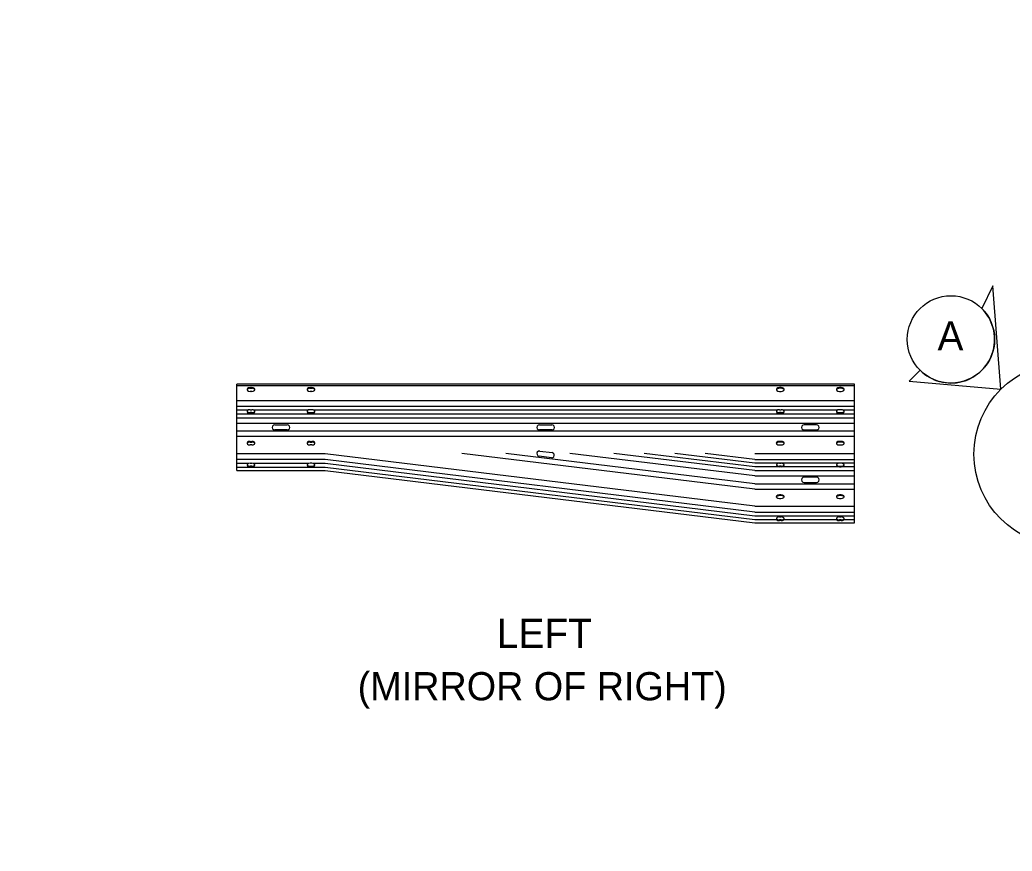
# Model space of a CAD drawing. Extents: x 34446 to 262144, y 33903 to 262144.
# Drawn here: x 101317 to 101879, y 100430 to 100902 of the extents above; entities that cross this region are included whole.
import ezdxf

# ---------------------------------------------------------------- set-up
doc = ezdxf.new("R2010")
doc.units = 0
for name, color, linetype in [('Level 12', 7, 'Continuous'), ('Level 15', 7, 'Continuous'), ('Level 20', 7, 'Continuous'), ('Level 5', 7, 'Continuous'), ('Level 9', 7, 'Continuous')]:
    doc.layers.add(name, color=color, linetype=linetype)

msp = doc.modelspace()

# ---------------------------------------------------------------- linework, layer by layer
at = {"layer": 'Level 12'}
for p, q in [((101790.09, 100695.07), (101440.09, 100695.07)), ((101440.09, 100646.07), (101440.09, 100695.07)), ((101790.09, 100616.5), (101790.09, 100695.07)), ((101440.09, 100646.07), (101490.09, 100646.07)), ((101490.09, 100646.07), (101733.71, 100616.5)), ((101733.71, 100616.5), (101790.09, 100616.5))]:
    msp.add_line(p, q, dxfattribs=at)
for points in [[(101461.59, 100672.06), (101468.59, 100672.06)], [(101468.59, 100669.08), (101461.59, 100669.08)], [(101611.59, 100672.06), (101618.59, 100672.06)], [(101618.59, 100669.08), (101611.59, 100669.08)], [(101768.59, 100672.06), (101761.59, 100672.06)], [(101761.59, 100669.08), (101768.59, 100669.08)], [(101611.77, 100657.16), (101618.71, 100656.32)], [(101618.35, 100653.35), (101611.4, 100654.2)], [(101768.59, 100642.3), (101761.59, 100642.3)], [(101761.59, 100639.32), (101768.59, 100639.32)]]:
    msp.add_lwpolyline(points, dxfattribs=at)
for centre, major_axis, start_param, end_param in [((101461.59, 100670.57), (-1.5, 0), 4.712389, 7.853982), ((101468.59, 100670.57), (-1.5, 0), 1.570796, 4.712389), ((101611.59, 100670.57), (-1.5, 0), 4.712389, 7.853982), ((101618.59, 100670.57), (-1.5, 0), 1.570796, 4.712389), ((101761.59, 100670.57), (1.5, 0), 1.570796, 4.712389), ((101768.59, 100670.57), (1.5, 0), 4.712389, 7.853982), ((101611.58, 100655.68), (-1.5, 0), 4.590604, 7.732197), ((101618.53, 100654.83), (-1.5, 0), 1.449011, 4.590604), ((101761.59, 100640.81), (1.5, 0), 1.570796, 4.712389), ((101768.59, 100640.81), (1.5, 0), 4.712389, 7.853982)]:
    msp.add_ellipse(centre, major_axis=major_axis, ratio=0.994924, start_param=start_param, end_param=end_param, dxfattribs=at)
at = {"layer": 'Level 15'}
msp.add_circle((101909.84, 100655.41), 52, dxfattribs=at)
at = {"layer": 'Level 5'}
msp.add_spline([(100965.33, 100576.22), (100979.73, 100581.07), (100976.65, 100587.06), (100980.64, 100590.15), (100978.82, 100594.87), (100978.82, 100594.87), (100972.35, 100605.26)], degree=3, dxfattribs=at)
at = {"layer": 'Level 9'}
for p, q in [((101868.48, 100750.85), (101862.3, 100737.95)), ((101873.07, 100692.18), (101868.48, 100750.85)), ((101827.29, 100702.95), (101821.11, 100696.76)), ((101821.11, 100696.76), (101873.07, 100692.18)), ((101790.09, 100694.19), (101440.09, 100694.19)), ((101790.09, 100694.19), (101440.09, 100694.19)), ((101447.66, 100693.1), (101448.53, 100693.1)), ((101447.66, 100692.7), (101448.53, 100692.7)), ((101448.53, 100690.98), (101447.66, 100690.98)), ((101481.66, 100693.1), (101482.53, 100693.1)), ((101481.66, 100692.7), (101482.53, 100692.7)), ((101482.53, 100690.98), (101481.66, 100690.98)), ((101748.53, 100693.1), (101747.66, 100693.1)), ((101748.53, 100692.7), (101747.66, 100692.7)), ((101747.66, 100690.98), (101748.53, 100690.98)), ((101782.53, 100693.1), (101781.66, 100693.1)), ((101782.53, 100692.7), (101781.66, 100692.7)), ((101781.66, 100690.98), (101782.53, 100690.98)), ((101790.09, 100685.65), (101440.09, 100685.65)), ((101790.09, 100682.41), (101440.09, 100682.41)), ((101446.31, 100680.22), (101440.09, 100680.22)), ((101447.66, 100680.56), (101448.53, 100680.56)), ((101480.31, 100680.22), (101449.88, 100680.22)), ((101482.53, 100680.56), (101481.66, 100680.56)), ((101746.31, 100680.22), (101483.88, 100680.22)), ((101747.66, 100680.56), (101748.53, 100680.56)), ((101780.31, 100680.22), (101749.88, 100680.22)), ((101782.53, 100680.56), (101781.66, 100680.56)), ((101790.09, 100680.22), (101783.88, 100680.22)), ((101790.09, 100678.02), (101440.09, 100678.02)), ((101790.09, 100675.83), (101440.09, 100675.83)), ((101448.53, 100678.92), (101447.66, 100678.92)), ((101448.53, 100678.51), (101447.66, 100678.51)), ((101481.66, 100678.92), (101482.53, 100678.92)), ((101481.66, 100678.51), (101482.53, 100678.51)), ((101748.53, 100678.92), (101747.66, 100678.92)), ((101748.53, 100678.51), (101747.66, 100678.51)), ((101781.66, 100678.92), (101782.53, 100678.92)), ((101781.66, 100678.51), (101782.53, 100678.51)), ((101790.09, 100672.8), (101440.09, 100672.8)), ((101790.09, 100668.35), (101440.09, 100668.35)), ((101790.09, 100665.32), (101440.09, 100665.32)), ((101447.66, 100662.63), (101448.53, 100662.63)), ((101481.69, 100662.63), (101482.56, 100662.63)), ((101748.5, 100662.63), (101747.63, 100662.63)), ((101782.53, 100662.63), (101781.66, 100662.63)), ((101447.66, 100662.23), (101448.53, 100662.23)), ((101448.53, 100660.58), (101447.66, 100660.58)), ((101481.69, 100662.23), (101482.56, 100662.23)), ((101482.56, 100660.58), (101481.69, 100660.58)), ((101748.5, 100662.23), (101747.63, 100662.23)), ((101747.63, 100660.58), (101748.5, 100660.58)), ((101782.53, 100662.23), (101781.66, 100662.23)), ((101781.66, 100660.58), (101782.53, 100660.58)), ((101490.09, 100655.5), (101440.09, 100655.5)), ((101490.09, 100655.5), (101440.09, 100655.5)), ((101490.09, 100652.26), (101440.09, 100652.26)), ((101490.09, 100652.26), (101440.09, 100652.26)), ((101733.71, 100625.83), (101490.09, 100655.5)), ((101733.71, 100622.4), (101490.09, 100652.26)), ((101733.71, 100635.57), (101567.67, 100655.79)), ((101733.71, 100638.6), (101592.56, 100655.79)), ((101733.71, 100643.02), (101628.86, 100655.79)), ((101733.71, 100646.05), (101653.75, 100655.79)), ((101733.71, 100648.15), (101671, 100655.79)), ((101733.71, 100650.25), (101688.25, 100655.79)), ((101733.71, 100652.35), (101705.5, 100655.79)), ((101733.71, 100655.79), (101790.09, 100655.79)), ((101733.71, 100652.35), (101790.09, 100652.35)), ((101446.68, 100650.07), (101440.09, 100650.07)), ((101490.09, 100647.87), (101440.09, 100647.87)), ((101490.09, 100647.87), (101440.09, 100647.87)), ((101447.66, 100650.23), (101448.53, 100650.23)), ((101448.53, 100648.59), (101447.66, 100648.59)), ((101448.53, 100648.18), (101447.66, 100648.18)), ((101480.68, 100650.07), (101449.51, 100650.07)), ((101482.53, 100650.23), (101481.66, 100650.23)), ((101481.66, 100648.59), (101482.53, 100648.59)), ((101481.66, 100648.18), (101482.53, 100648.18)), ((101490.09, 100650.07), (101483.51, 100650.07)), ((101733.71, 100620.3), (101490.09, 100650.07)), ((101733.71, 100618.19), (101490.09, 100647.87)), ((101790.09, 100650.25), (101733.71, 100650.25)), ((101790.09, 100648.15), (101733.71, 100648.15)), ((101733.71, 100646.05), (101790.09, 100646.05)), ((101747.66, 100650.23), (101748.53, 100650.23)), ((101748.53, 100648.59), (101747.66, 100648.59)), ((101748.53, 100648.18), (101747.66, 100648.18)), ((101782.53, 100650.23), (101781.66, 100650.23)), ((101781.66, 100648.59), (101782.53, 100648.59)), ((101781.66, 100648.18), (101782.53, 100648.18)), ((101733.71, 100643.02), (101790.09, 100643.02)), ((101733.71, 100638.6), (101790.09, 100638.6)), ((101733.71, 100635.57), (101790.09, 100635.57)), ((101748.47, 100632.3), (101747.6, 100632.3)), ((101748.47, 100631.9), (101747.6, 100631.9)), ((101747.6, 100630.25), (101748.47, 100630.25)), ((101782.53, 100632.3), (101781.66, 100632.3)), ((101782.53, 100631.9), (101781.66, 100631.9)), ((101781.66, 100630.25), (101782.53, 100630.25)), ((101733.71, 100625.83), (101790.09, 100625.83)), ((101733.71, 100622.4), (101790.09, 100622.4)), ((101790.09, 100620.3), (101733.71, 100620.3)), ((101746.11, 100618.19), (101733.71, 100618.19)), ((101747.66, 100619.8), (101748.53, 100619.8)), ((101748.53, 100618.08), (101747.66, 100618.08)), ((101748.53, 100617.68), (101747.66, 100617.68)), ((101780.11, 100618.19), (101750.07, 100618.19)), ((101781.66, 100619.8), (101782.53, 100619.8)), ((101782.53, 100618.08), (101781.66, 100618.08)), ((101782.53, 100617.68), (101781.66, 100617.68)), ((101790.09, 100618.19), (101784.07, 100618.19))]:
    msp.add_line(p, q, dxfattribs=at)
msp.add_circle((101844.8, 100720.45), 24.75, dxfattribs=at)
msp.add_arc((101844.8, 100720.45), 24.75, 224.9978, 45.0022, dxfattribs=at)
for centre, major_axis, ratio, start_param, end_param in [((101447.66, 100692.04), (-1.8, 0), 0.587551, 4.712389, 7.853982), ((101447.66, 100691.64), (-1.8, 0), 0.587551, 4.712389, 6.092062), ((101448.53, 100692.04), (-1.8, 0), 0.587551, 1.570796, 4.712389), ((101448.53, 100691.64), (-1.8, 0), 0.587551, 3.332716, 4.712389), ((101481.66, 100692.04), (-1.8, 0), 0.587551, 4.712389, 7.853982), ((101481.66, 100691.64), (-1.8, 0), 0.587551, 4.712389, 6.092062), ((101482.53, 100692.04), (-1.8, 0), 0.587551, 1.570796, 4.712389), ((101482.53, 100691.64), (-1.8, 0), 0.587551, 3.332716, 4.712389), ((101747.66, 100692.04), (-1.8, 0), 0.587551, 4.712389, 7.853982), ((101747.66, 100691.64), (-1.8, 0), 0.587551, 4.712389, 6.092062), ((101748.53, 100692.04), (-1.8, 0), 0.587551, 1.570796, 4.712389), ((101748.53, 100691.64), (-1.8, 0), 0.587551, 3.332716, 4.712389), ((101781.66, 100692.04), (-1.8, 0), 0.587551, 4.712389, 7.853982), ((101781.66, 100691.64), (-1.8, 0), 0.587551, 4.712389, 6.092062), ((101782.53, 100692.04), (-1.8, 0), 0.587551, 1.570796, 4.712389), ((101782.53, 100691.64), (-1.8, 0), 0.587551, 3.332716, 4.712389), ((101447.66, 100679.54), (-1.8, 0), 0.568261, 4.712389, 7.853982), ((101447.66, 100679.94), (-1.8, 0), 0.568261, 0.197752, 1.570796), ((101448.53, 100679.54), (-1.8, 0), 0.568261, 1.570796, 4.712389), ((101448.53, 100679.94), (-1.8, 0), 0.568261, 1.570796, 2.943841), ((101481.66, 100679.54), (-1.8, 0), 0.568261, 4.712389, 7.853982), ((101481.66, 100679.94), (-1.8, 0), 0.568261, 0.197752, 1.570796), ((101482.53, 100679.54), (-1.8, 0), 0.568261, 1.570796, 4.712389), ((101482.53, 100679.94), (-1.8, 0), 0.568261, 1.570796, 2.943841), ((101747.66, 100679.54), (-1.8, 0), 0.568261, 4.712389, 7.853982), ((101747.66, 100679.94), (-1.8, 0), 0.568261, 0.197752, 1.570796), ((101748.53, 100679.54), (-1.8, 0), 0.568261, 1.570796, 4.712389), ((101748.53, 100679.94), (-1.8, 0), 0.568261, 1.570796, 2.943841), ((101781.66, 100679.54), (-1.8, 0), 0.568261, 4.712389, 7.853982), ((101781.66, 100679.94), (-1.8, 0), 0.568261, 0.197752, 1.570796), ((101782.53, 100679.54), (-1.8, 0), 0.568261, 1.570796, 4.712389), ((101782.53, 100679.94), (-1.8, 0), 0.568261, 1.570796, 2.943841), ((101447.66, 100661.6), (1.8, 0), 0.568261, 1.570796, 4.712389), ((101448.53, 100661.6), (1.8, 0), 0.568261, 4.712389, 7.853982), ((101481.69, 100661.6), (1.8, 0), 0.568261, 1.570796, 4.712389), ((101482.56, 100661.6), (1.8, 0), 0.568261, 4.712389, 7.853982), ((101747.63, 100661.6), (1.8, 0), 0.568261, 1.570796, 4.712389), ((101748.5, 100661.6), (1.8, 0), 0.568261, 4.712389, 7.853982), ((101781.66, 100661.6), (1.8, 0), 0.568261, 1.570796, 4.712389), ((101782.53, 100661.6), (1.8, 0), 0.568261, 4.712389, 7.853982), ((101447.66, 100661.2), (1.8, 0), 0.568261, 1.570796, 2.943841), ((101448.53, 100661.2), (1.8, 0), 0.568261, 0.197752, 1.570796), ((101481.69, 100661.2), (1.8, 0), 0.568261, 1.570796, 2.943841), ((101482.56, 100661.2), (1.8, 0), 0.568261, 0.197752, 1.570796), ((101747.63, 100661.2), (1.8, 0), 0.568261, 1.570796, 2.943841), ((101748.5, 100661.2), (1.8, 0), 0.568261, 0.197752, 1.570796), ((101781.66, 100661.2), (1.8, 0), 0.568261, 1.570796, 2.943841), ((101782.53, 100661.2), (1.8, 0), 0.568261, 0.197752, 1.570796), ((101447.66, 100649.21), (-1.8, 0), 0.568261, 4.712389, 7.853982), ((101447.66, 100649.61), (-1.8, 0), 0.568261, 0.197752, 1.570796), ((101448.53, 100649.21), (-1.8, 0), 0.568261, 1.570796, 4.712389), ((101448.53, 100649.61), (-1.8, 0), 0.568261, 1.570796, 2.943841), ((101481.66, 100649.21), (-1.8, 0), 0.568261, 4.712389, 7.853982), ((101481.66, 100649.61), (-1.8, 0), 0.568261, 0.197752, 1.570796), ((101482.53, 100649.21), (-1.8, 0), 0.568261, 1.570796, 4.712389), ((101482.53, 100649.61), (-1.8, 0), 0.568261, 1.570796, 2.943841), ((101747.66, 100649.21), (-1.8, 0), 0.568261, 4.712389, 7.853982), ((101747.66, 100649.61), (-1.8, 0), 0.568261, 0.197752, 1.570796), ((101748.53, 100649.21), (-1.8, 0), 0.568261, 1.570796, 4.712389), ((101748.53, 100649.61), (-1.8, 0), 0.568261, 1.570796, 2.943841), ((101781.66, 100649.21), (-1.8, 0), 0.568261, 4.712389, 7.853982), ((101781.66, 100649.61), (-1.8, 0), 0.568261, 0.197752, 1.570796), ((101782.53, 100649.21), (-1.8, 0), 0.568261, 1.570796, 4.712389), ((101782.53, 100649.61), (-1.8, 0), 0.568261, 1.570796, 2.943841), ((101747.6, 100631.27), (1.8, 0), 0.568261, 1.570796, 4.712389), ((101747.6, 100630.87), (1.8, 0), 0.568261, 1.570796, 2.943841), ((101748.47, 100631.27), (1.8, 0), 0.568261, 4.712389, 7.853982), ((101748.47, 100630.87), (1.8, 0), 0.568261, 0.197752, 1.570796), ((101781.66, 100631.27), (1.8, 0), 0.568261, 1.570796, 4.712389), ((101781.66, 100630.87), (1.8, 0), 0.568261, 1.570796, 2.943841), ((101782.53, 100631.27), (1.8, 0), 0.568261, 4.712389, 7.853982), ((101782.53, 100630.87), (1.8, 0), 0.568261, 0.197752, 1.570796), ((101747.66, 100618.74), (1.8, 0), 0.587551, 1.570796, 4.712389), ((101747.66, 100619.14), (1.8, 0), 0.587551, 3.332716, 4.712389), ((101748.53, 100618.74), (1.8, 0), 0.587551, 4.712389, 7.853982), ((101748.53, 100619.14), (1.8, 0), 0.587551, 4.712389, 6.092062), ((101781.66, 100618.74), (1.8, 0), 0.587551, 1.570796, 4.712389), ((101781.66, 100619.14), (1.8, 0), 0.587551, 3.332716, 4.712389), ((101782.53, 100618.74), (1.8, 0), 0.587551, 4.712389, 7.853982), ((101782.53, 100619.14), (1.8, 0), 0.587551, 4.712389, 6.092062)]:
    msp.add_ellipse(centre, major_axis=major_axis, ratio=ratio, start_param=start_param, end_param=end_param, dxfattribs=at)

# ---------------------------------------------------------------- texts
at = {"layer": 'Level 20'}
for s, height, p in [('A', 16.5, (101837.17, 100714.16)), ('LEFT', 16.5, (101587.39, 100545.56)), ('(MIRROR OF RIGHT)', 16, (101508.57, 100515.81))]:
    msp.add_text(s, height=height, dxfattribs=at).set_placement(p)

doc.saveas('drawing.dxf')
